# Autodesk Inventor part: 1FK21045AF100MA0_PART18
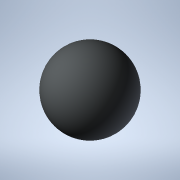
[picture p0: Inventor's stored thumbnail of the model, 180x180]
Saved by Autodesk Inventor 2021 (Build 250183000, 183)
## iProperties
Created: 2025-04
Part Number: 1FK21045AF100MA0_PART18
Material: Generic
Catalog Web Link: www.3dfindit.com
Description: -Servo synchronous motor
Document SubType Name: Modeling
Designer: psAdmin
Mass: 0.137258 g
Surface Area: 1.2868 cm^2
Volume: 0.137258 cm^3
Density: 1 g/cm^3
Appearance: PSOLRGB-212-217-219
Category: PARTsolutions
Title: 1FK21045AF100MA0_PART18
Author: Cadenas PARTsolutions
Comments: Servo synchronous motor
Sending System: PARTsolutions
Preprocessor: ST-DEVELOPER v19.3
PSOL_IDENT_0: {$CADENAS_DATA/23d-libs/siemens_ag/_cat_/52/6b/1fk21045af100ma0.prj},216 {VTYP=3D},{NB=1FK21045AF100
PSOL_IDENT_1: MA0_PART18},{LINA=1FK21045AF100MA0_PART18},{NN=1FK21045AF100MA0_PART18},{NOPRJ=TRUE},{DATE=19.08.202
PSOL_IDENT_2: 5 14:00:38},{GEOMDATE=30.07.2025 02:01:45},{VERSION=},{LINEID=10},{WBVAR=},{WBNUMERIC=}  {NB=1FK2104
PSOL_IDENT_3: 5AF100MA0_PART18},{LINA=1FK21045AF100MA0_PART18},{KT=DUMMY},{PREVIEW=../../../_pool_/cb/72/p_d211_xx
PSOL_IDENT_4: _00434j.png},{DESCSHORT=SIMOTICS S-1FK2 HD, SINAMICS S210 3AC 400V-480V, 2.4 Nm, 3000 rpm},{DESCLONG=
PSOL_IDENT_5: SIMOTICS S-1FK2 HD servo motor M0=2.4 Nm; PN = 0.75 kW at nN=3000 rpm (380-480 V); PN = 0.375 kW at
PSOL_IDENT_6: nN=1500 rpm (200-240 V); with holding brake; degree of protection IP64; cylindrical shaft D19x40mm;
PSOL_IDENT_7: absolute encoder 22-bit + 12-bit multiturn (encoder AM22DQC); with OCC interface; plug size M17, rot
PSOL_IDENT_8: atable; SIMOTICS S-1FK2 servomotorfor a wide range of uses in industrial environments. SIMOTICS S‑1F
PSOL_IDENT_9: K2 servomotors are compact synchronous motors with a high dynamic performance that set themselves ap
PSOL_IDENT_10: art as a result of their high power density, degree of protection and overload capability. The motor
PSOL_IDENT_11: s are available in two variants: as High Dynamic variant (highest dynamic performance as a result of
PSOL_IDENT_12: the low intrinsic moment of inertia for applications demanding a high dynamic performance with low
PSOL_IDENT_13: moved masses) - and as Compact variant (precise and stable closed-loop control for medium up to larg
PSOL_IDENT_14: e moved masses as a result of a medium intrinsic moment of inertia). SIMOTICSS‑1FK2 servomotors full
PSOL_IDENT_15: y exploit their strengths in a system with the SINAMICSS210 frequency converter and simple connectio
PSOL_IDENT_16: n using the one cable connection (OCC). Advantages include the short control and positioning times,
PSOL_IDENT_17: fast and precise correction of disturbing quantities as well as stable control with a high dynamic p
PSOL_IDENT_18: erformance. The servo motors can be configured to address a wide range of requirements. For example
PSOL_IDENT_19: with and without holding brake, IP64 or IP65 degree of protection, singleturn or multiturn absolute
PSOL_IDENT_20: encoders - to name just a few. Further, the servomotors are available in different shaft heights ext
PSOL_IDENT_21: ending from 20 to 100. A shaft sealing ring is available to achieve an IP65 degree of protection and
PSOL_IDENT_22: for subsequent mounting at the motor or as spare part. SIMOTICS - the optimum motor for each and ev
PSOL_IDENT_23: ery motion control application.},{INTNO=804766906411},{SUPPLIERALTNO=1FK2104-5AF10-0MA0},{MANUID=1FK
PSOL_IDENT_24: 21045AF100MA0},{MANUNAME=Siemens},{MANUTYPEDESC=Synchronous motor 1FK2-HD 2.4 NM},{AAU732=SIMOTICS},
PSOL_IDENT_25: {AAO057=S-1FK2},{AAU734=SIMOTICS S-1FK2 HD servo motor M0=2.4 Nm; PN = 0.75 kW at nN=3000 rpm (380-4
PSOL_IDENT_26: 80 V); PN = 0.375 kW at nN=1500 rpm (200-240 V); with holding brake; degree of protection IP64; cyli
PSOL_IDENT_27: ndrical shaft D19x40mm; absolute encoder 22-bit + 12-bit multiturn (encoder AM22DQC); with OCC inter
PSOL_IDENT_28: face; plug size M17, rotatable;},{AAW338=Synchronous motor 1FK2-HD 2.4 NM},{AAO742=SIMOTICS},{AAO663=
PSOL_IDENT_29: 4042948693070},{NOCUPEROU=1},{PRICEQUANTITY=1},{QUANTITYMIN=1},{QUANTITYINT=1},{CTN=85015100},{COO=D
PSOL_IDENT_30: E},{AAO676=1FK2104-5AF10-0MA0},{AAO677=Siemens AG},{ORDERUNIT=C62},{CONTENTUNIT=C62}
NB: 1FK21045AF100MA0_PART18
NT: Servo synchronous motor
NBSYN: $MANUID._PART18
LINA: 1FK21045AF100MA0_PART18
CATALOG: SIEMENS
PREVIEW: ../../../_pool_/cb/72/p_d211_xx_00434j.png
DESCSHORT: SIMOTICS S-1FK2 HD, SINAMICS S210 3AC 400V-480V, 2.4 Nm, 3000 rpm
DESCLONG: SIMOTICS S-1FK2 HD servo motor M0=2.4 Nm; PN = 0.75 kW at nN=3000 rpm (380-480 V); PN = 0.375 kW at nN=1500 rpm (200-240 V); with holding brake; degree of prote
INTNO: 804766906411
SUPPLIERALTNO: 1FK2104-5AF10-0MA0
MANUID: 1FK21045AF100MA0
MANUNAME: Siemens
MANUTYPEDESC: Synchronous motor 1FK2-HD 2.4 NM
AAU732: SIMOTICS
AAO057: S-1FK2
AAU734: SIMOTICS S-1FK2 HD servo motor M0=2.4 Nm; PN = 0.75 kW at nN=3000 rpm (380-480 V); PN = 0.375 kW at nN=1500 rpm (200-240 V); with holding brake; degree of prote
AAW338: Synchronous motor 1FK2-HD 2.4 NM
AAO742: SIMOTICS
AAO663: 4042948693070.0
NOCUPEROU: 1
PRICEQUANTITY: 1
QUANTITYMIN: 1
QUANTITYINT: 1
CTN: 85015100
COO: DE
ARTICLENO: 1FK21045AF100MA0_PART18
BOMINFO: 1FK21045AF100MA0_PART18
CREATOR: CADENAS GmbH
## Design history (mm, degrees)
feature "2025_04_17_15_34_52_0317"
body "Solid1"
